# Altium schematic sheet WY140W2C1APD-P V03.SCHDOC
size A3; PageSetup: Record=PageOptions¦CenterHorizontal=True¦CenterVertical=True¦PrintScale=0.71¦XCorrection=1.00¦YCorrection=1.00¦PrintKind=0¦BorderSize=5000000¦LeftOffset=0¦BottomOffset=0¦Orientation=2¦PaperLength=1000¦PaperWidth=1000¦Scale=100¦PaperSource=7¦PrintQuality=-4¦MediaType=1¦DitherType=10¦PaperKind=A4¦PrintScaleMode=1
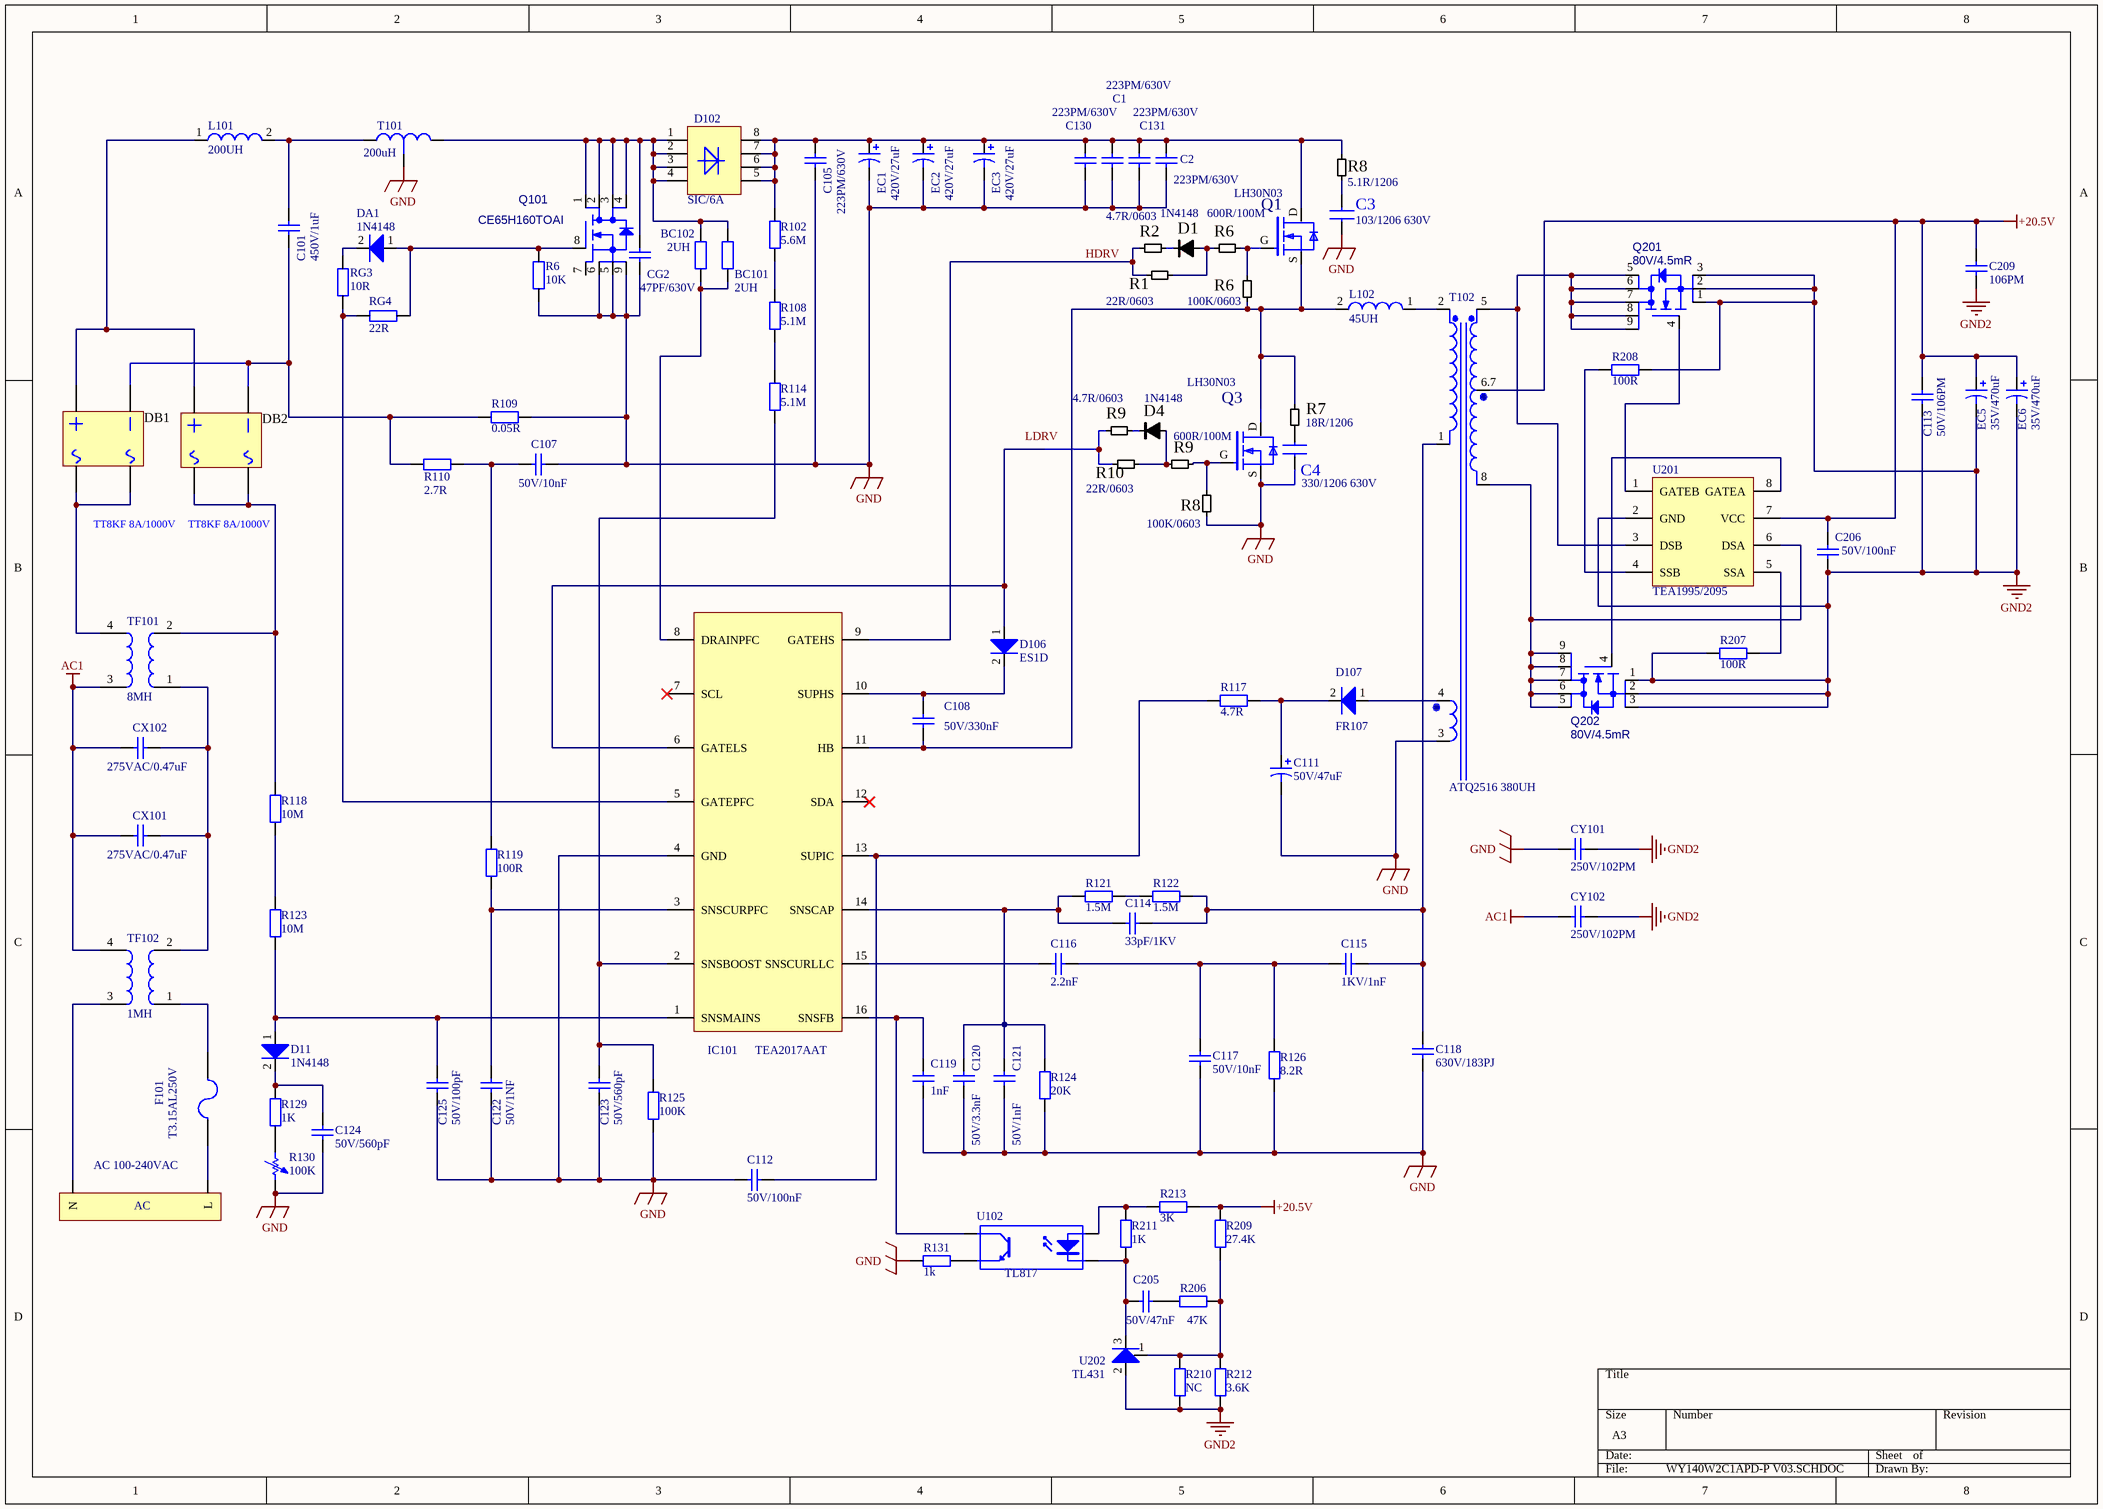
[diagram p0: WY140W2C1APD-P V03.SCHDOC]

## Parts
(Parts that share a designator on the sheet are numbered #1, #2 ... from top to bottom, then left to right.)
AC_100-240VAC  AC  [C0N-3P-P3.96-1]
BC101  2UH  [1206(W)]
BC102  2UH  [1206(W)]
C1  223PM/630V  [1206C(W)]
C2  223PM/630V  [1206C(W)]
C3  103/1206 630V  [C0603]
C4  330/1206 630V  [C0603]
C101  450V/1uF  [XC-17.5X5.5-P15-卧]
C105  223PM/630V  [1206C(W)]
C107  50V/10nF  [0805C(W)]
C108  50V/330nF  [0805C(W)]
C111  50V/47uF  [EC-8X16-P3.5-C]
C112  50V/100nF  [0805C(W)]
C113  50V/106PM  [0805C(W)]
C114  33pF/1KV  [CC-6.5X2.5-P5]
C115  1KV/1nF  [CC-8X2.5-P5]
C116  2.2nF  [0603C(W)]
C117  50V/10nF  [0603C(W)]
C118  630V/183PJ  [MC-15.5X6.5-P12.5]
C119  1nF  [0603C(W)]
C120  50V/3.3nF  [0603C(W)]
C121  50V/1nF  [0603C(W)]
C122  50V/1NF  [0603C(W)]
C123  50V/560pF  [0603C(W)]
C124  50V/560pF  [0603C(W)]
C125  50V/100pF  [0603C(W)]
C130  223PM/630V  [1206C(W)]
C131  223PM/630V  [1206C(W)]
C205  50V/47nF  [0603C(W)]
C206  50V/100nF  [0603C(W)]
C209  106PM  [CC-6.5X2.5-P5]
CG2  47PF/630V  [1206C(W)]
CX101  275VAC/0.47uF  [XC-13X4-P10-卧]
CX102  275VAC/0.47uF  [XC-13X4-P10-卧]
CY101  250V/102PM  [YC-10.5X5-P7.5]
CY102  250V/102PM  [YC-10.5X5-P7.5]
D1  1N4148  [SOD-323]
D4  1N4148  [SOD-323]
D11  1N4148  [SOD-323]
D102  SIC/6A  [SSOP-8]
D106  ES1D  [SMAF]
D107  FR107  [SOD-80]
DA1  1N4148  [SOD-323]
DB1  TT8KF 8A/1000V  [GBU]
DB2  TT8KF 8A/1000V  [GBU]
EC1  420V/27uF  [EC16*25]
EC2  420V/27uF  [EC16*25]
EC3  420V/27uF  [EC16*25]
EC5  35V/470uF  [EC-10X20-P5-C]
EC6  35V/470uF  [EC-10X20-P5-C]
F101  T3.15AL250V  [F-8.5X4-P5]
IC101  TEA2017AAT  [SO-16(P5.6)]
L101  200UH  [L10*6*5]
L102  45UH  [TF-RM5]
Q1  LH30N03  [DFN3*3]
Q3  LH30N03  [DFN3*3]
Q101  CE65H160TOAI  [DFN8*8]
Q201  80V/4.5mR  [DFN3*3-9]
Q202  80V/4.5mR  [DFN3*3-9]
R1  22R/0603  [R0603]
R2  4.7R/0603  [R0603]
R6#1  600R/100M  [R0603]
R6#2  10K  [R0805A]
R6#3  100K/0603  [R0603]
R7  18R/1206  [R0603]
R8#1  5.1R/1206  [R0603]
R8#2  100K/0603  [R0603]
R9#1  4.7R/0603  [R0603]
R9#2  600R/100M  [R0603]
R10  22R/0603  [R0603]
R102  5.6M  [1206(W)]
R108  5.1M  [1206(W)]
R109  0.05R  [2512(W)]
R110  2.7R  [0603(W)]
R114  5.1M  [1206(W)]
R117  4.7R  [1206(W)]
R118  10M  [1206(W)]
R119  100R  [0603(W)]
R121  1.5M  [1206]
R122  1.5M  [1206]
R123  10M  [1206(W)]
R124  20K  [0603(W)]
R125  100K  [0603(W)]
R126  8.2R  [0805(W)]
R129  1K  [0603(W)]
R130  100K  [0603(W)]
R131  1k  [0603(W)]
R206  47K  [0603(W)]
R207  100R  [1206(W)]
R208  100R  [1206(W)]
R209  27.4K  [0603(W)]
R210  NC  [0603(W)]
R211  1K  [0603(W)]
R212  3.6K  [0603(W)]
R213  3K  [0603(W)]
RG3  10R  [R0805A]
RG4  22R  [R0805A]
T101  200uH  [PQ2016/2+1]
T102  ATQ2516 380UH
TF101  8MH  [L-9.5X4.75X3.2C]
TF102  1MH  [L-9.5X4.75X3.2C]
U102  TL817  [SO-4(P10)]
U201  TEA1995/2095  [SSOP-8]
U202  TL431  [SOT23]

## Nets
+20.5V: C113.1 C206.1 C209.1 EC5.1 EC6.1 R209.1 R213.2 T102.6.7 U201.7(VCC)
AC1: CX101.2 CX102.2 CY102.2 TF101.3 TF102.4
GND: C1.1 C2.1 C3.1 C4.1 C105.1 C107.1 C111.2 C112.1 C117.1 C118.1 C119.2 C120.1 C121.1 C122.1 C123.1 C124.1 C125.1 C130.1 C131.1 CG2.1 CY101.2 EC1.2 EC2.2 EC3.2 IC101.4(GND) Q3.S Q101.5(Source2) Q101.6(Source1) Q101.9(Source3) R6#2.2 R8#2.1 R109.1 R124.1 R125.1 R126.1 R130.2 R131.1 T101.2 T102.3
GND2: C113.2 C206.2 C209.2 CY101.1 CY102.1 EC5.2 EC6.2 Q201.1(Source1) Q201.2(Source2) Q201.3(Source3) Q202.1(Source1) Q202.2(Source2) Q202.3(Source3) R207.2 R208.1 R210.1 R212.1 U201.2(GND) U202.2(A)
HDRV: IC101.9(GATEHS) R1.2 R2.2
NetAC_100-240VAC_?1: AC_100-240VAC.?1(N) TF102.3
NetAC_100-240VAC_?2: AC_100-240VAC.?2(L) F101.1
NetBC101_1: BC101.1 BC102.1 CG2.2 D102.1(A) D102.2(A) D102.3(A) D102.4(A) Q101.1(Drain1) Q101.2(Drain2) Q101.3(Drain3) Q101.4(Drain4) T101.1
NetBC101_2: BC101.2 BC102.2 IC101.8(DRAINPFC)
NetC1_2: C1.2 C2.2 C105.2 C130.2 C131.2 D102.5(K) D102.6(K) D102.7(K) D102.8(K) EC1.1 EC2.1 EC3.1 Q1.D R8#1.1 R102.2
NetC3_2: C3.2 R8#1.2
NetC101_1: C101.1 DB1.4 DB2.4 R109.2 R110.1
NetC101_2: C101.2 L101.2 T101.3
NetC107_2: C107.2 R110.2 R119.1
NetC108_1: C108.1 IC101.11(HB) L102.2 Q1.S Q3.D R6#3.1 R7.1
NetC108_2: C108.2 D106.2(K) IC101.10(SUPHS)
NetC111_1: C111.1 D107.2(K) R117.1
NetC112_2: C112.2 IC101.13(SUPIC) R117.2
NetC114_1: C114.1 C115.1 C118.2 R122.1 T102.1
NetC114_2: C114.2 C120.2 C121.2 IC101.14(SNSCAP) R121.2 R124.2
NetC115_2: C115.2 C116.1 C117.2 R126.2
NetC116_2: C116.2 IC101.15(SNSCURLLC)
NetC119_1: C119.1 IC101.16(SNSFB) U102.4(C)
NetC122_2: C122.2 IC101.3(SNSCURPFC) R119.2
NetC123_2: C123.2 IC101.2(SNSBOOST) R114.1 R125.2
NetC124_2: C124.2 D11.2(K) R129.2
NetC125_2: C125.2 D11.1(A) IC101.1(SNSMAINS) R123.2
NetC205_1: C205.1 R211.1 U102.2(K) U202.3(K)
NetC205_2: C205.2 R206.1
NetCX101_1: CX101.1 CX102.1 TF101.1 TF102.2
NetD1_1: D1.1 R1.1 R6#1.2
NetD1_2: D1.2 R2.1
NetD4_1: D4.1 R9#2.2 R10.1
NetD4_2: D4.2 R9#1.1
NetD106_1: D106.1(A) IC101.6(GATELS) R9#1.2 R10.2
NetD107_1: D107.1(A) T102.4
NetDA1_1: DA1.1(A) Q101.8(Gate) R6#2.1 RG4.2
NetDA1_2: DA1.2(K) RG3.2
NetDB1_1: DB1.1 DB1.3 TF101.4
NetDB1_2: DB1.2 DB2.2 L101.1
NetDB2_1: DB2.1 DB2.3 R118.2 TF101.2
NetF101_2: F101.2 TF102.1
NetIC101_5: IC101.5(GATEPFC) RG3.1 RG4.1
NetL102_1: L102.1 T102.2
NetQ1_G: Q1.G R6#1.1 R6#3.2
NetQ3_G: Q3.G R8#2.2 R9#2.1
NetQ201_4: Q201.4(Gate) U201.1(GATEB)
NetQ201_5: Q201.5(Drain1) Q201.6(Drain2) Q201.7(Drain3) Q201.8(Drain4) Q201.9(Drain4) T102.5 U201.3(DSB)
NetQ202_4: Q202.4(Gate) U201.8(GATEA)
NetQ202_5: Q202.5(Drain1) Q202.6(Drain2) Q202.7(Drain3) Q202.8(Drain4) Q202.9(Drain4) T102.8 U201.6(DSA)
NetR102_1: R102.1 R108.2
NetR108_1: R108.1 R114.2
NetR118_1: R118.1 R123.1
NetR121_1: R121.1 R122.2
NetR129_1: R129.1 R130.1
NetR131_2: R131.2 U102.3(E)
NetR206_2: R206.2 R209.2 R210.2 R212.2 U202.1(G)
NetR207_1: R207.1 U201.5(SSA)
NetR208_2: R208.2 U201.4(SSB)
NetR211_2: R211.2 R213.1 U102.1(A)

Not connected (* = marked no-connect by the designer): C4 2; IC101 7(SCL)* 12(SDA)*; Q101 7(SK); R7 2

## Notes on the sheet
- Labels drawn without touching a wire or pin: LDRV

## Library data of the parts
AC_100-240VAC = CHN
BC101 BC102 R102 R108-R110 R114 R117-R119 R121-R126 R206-R210 R212 R213 = Res2: Resistor; Value: 1K
C1 C2 C101 C105 C107 C108 C112-C125 C130 C131 C205 C206 C209 CG2 CX101 CX102 CY101 CY102 = Cap: Capacitor; Value: 100pF
C3 C4 = CAP
C111 EC1-EC3 EC5 EC6 = Cap Pol1: Polarized Capacitor (Radial); Value: 100pF
D1 D4 = D11
D11 D106 D107 DA1 = Diode: Default Diode
D102 = DSOP-8
DB1 DB2 = DB107G
F101 = Fuse 2: Fuse
IC101 = IC16-S
L101 L102 = Inductor: Code_IEC: 1005; Value: 10mH
Q1 Q3 = MOS_E
Q101 = INN650D02: N MOS; Part Number 1: IRF6691 MT; Manufacturer 1: International Rectifier; Typical Rds(on) @10.0V: 1.2m; Voltage: 20V
Q201 Q202 = NMOS 8*8: N MOS; Part Number 1: IRF6691 MT; Manufacturer 1: International Rectifier; Typical Rds(on) @10.0V: 1.2m; Voltage: 20V
R1 R2 R6#1 R6#3 R7 R8#1 R8#2 R9#1 R9#2 R10 = R3
R6#2 RG3 RG4 = Res SMD: 贴片电阻
R129 R131 R211 = Res2: Resistor
R130 = Res Adj1: Variable Resistor; Value: 1K; Set Position: 0.5
T101 = Inductor-A: Inductor; Code_IEC: 1005; Value: 10mH
T102 = T1
TF101 TF102 = Trans: Transformer
U102 = Optoisolator1: 4-Pin Phototransistor Optocoupler
U201 = TEA1995
U202 = TL431: Default Diode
